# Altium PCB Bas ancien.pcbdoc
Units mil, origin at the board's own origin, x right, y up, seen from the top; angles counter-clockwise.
Board outline 2992.1 x 2852.4 mil, 2 copper layers (Top Layer, Bottom Layer), stack 62.2 mil thick; 28 components, 47 nets, 196 pads, 0 vias.
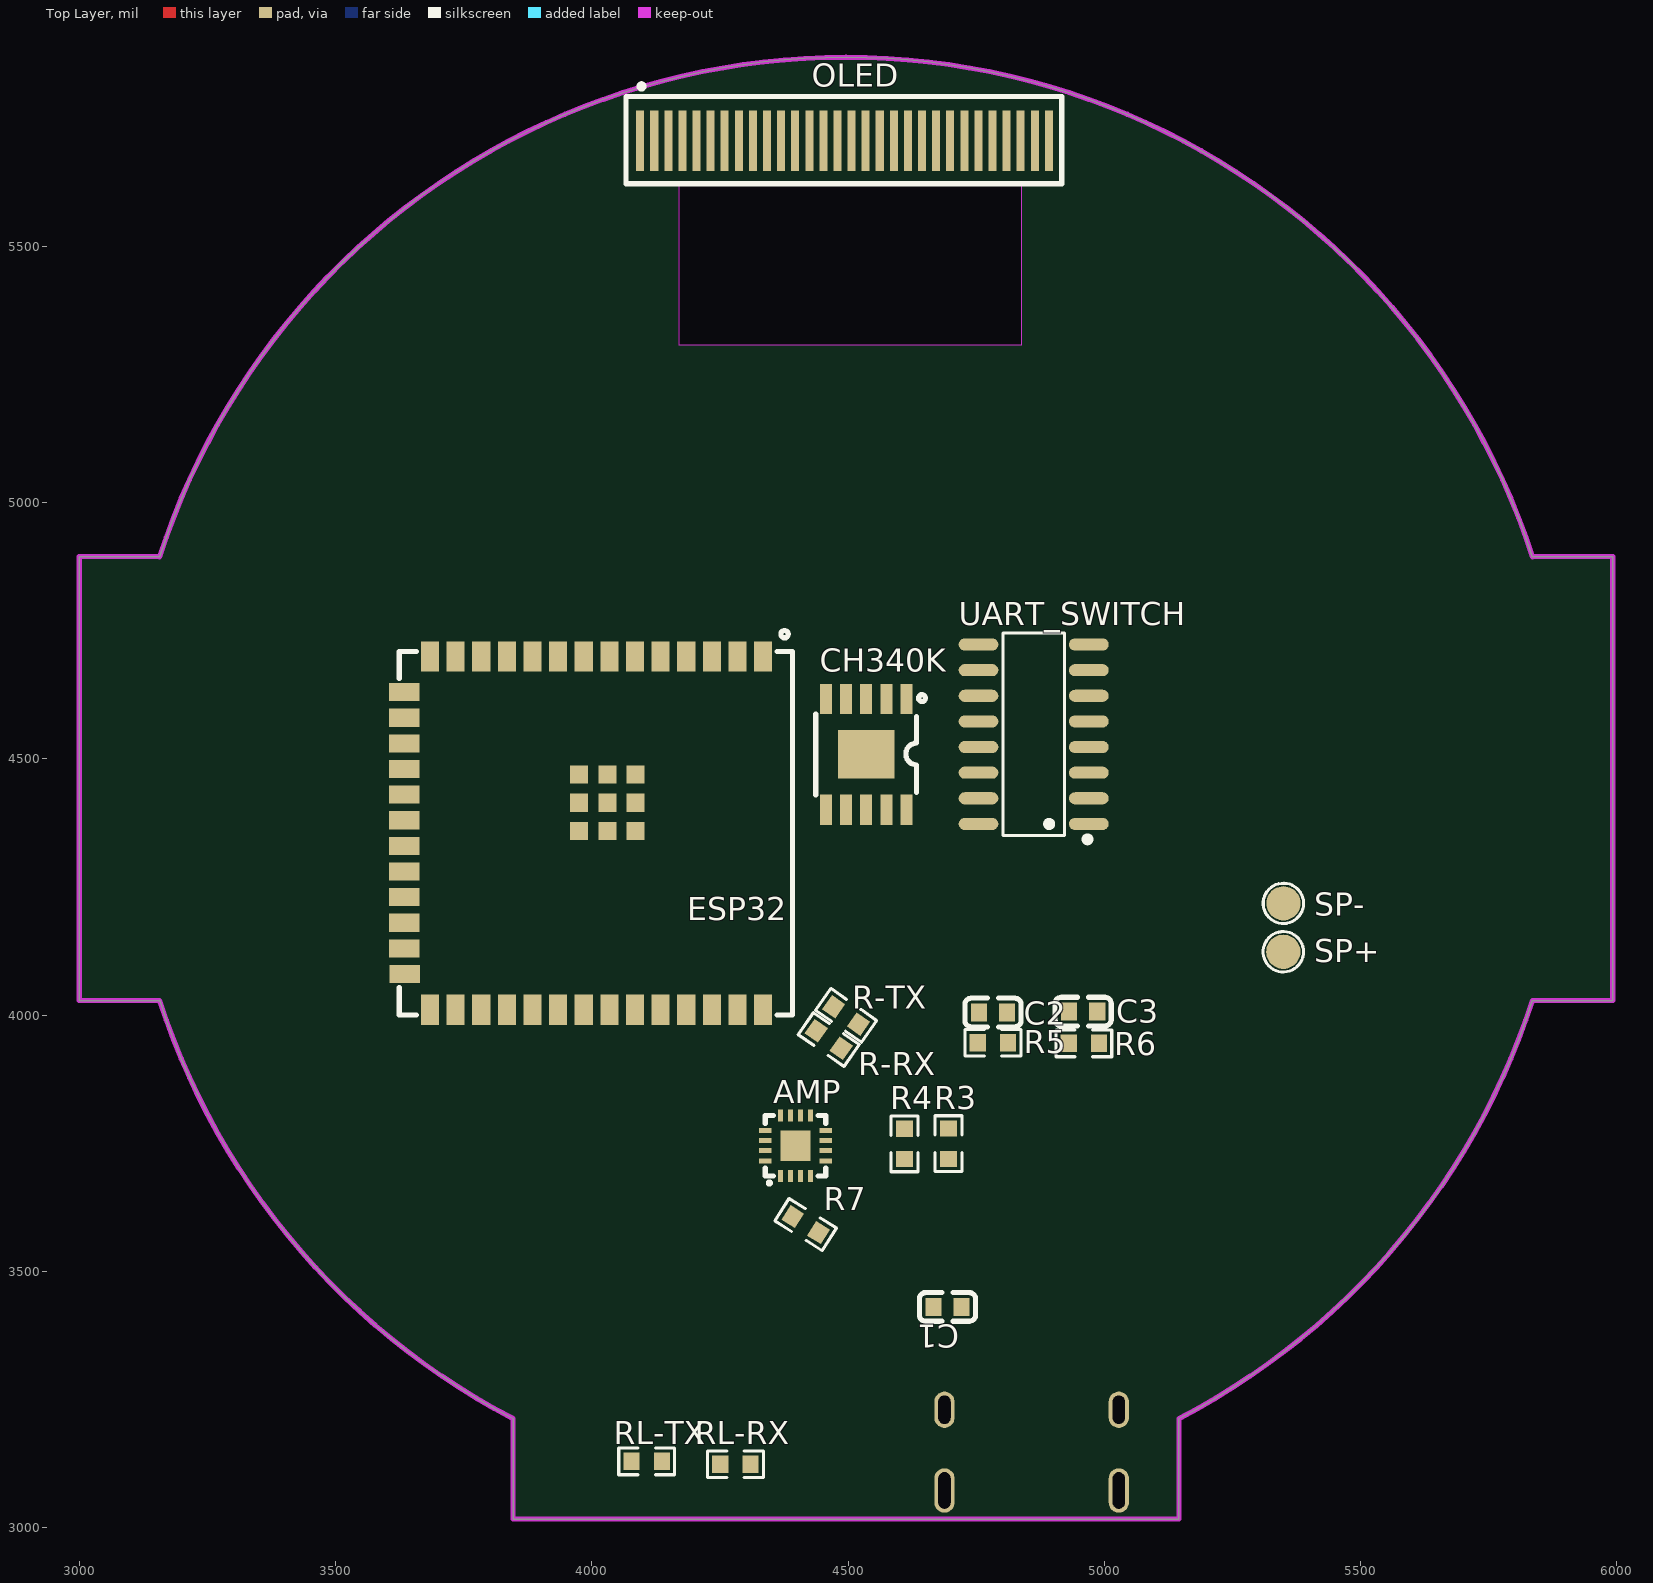
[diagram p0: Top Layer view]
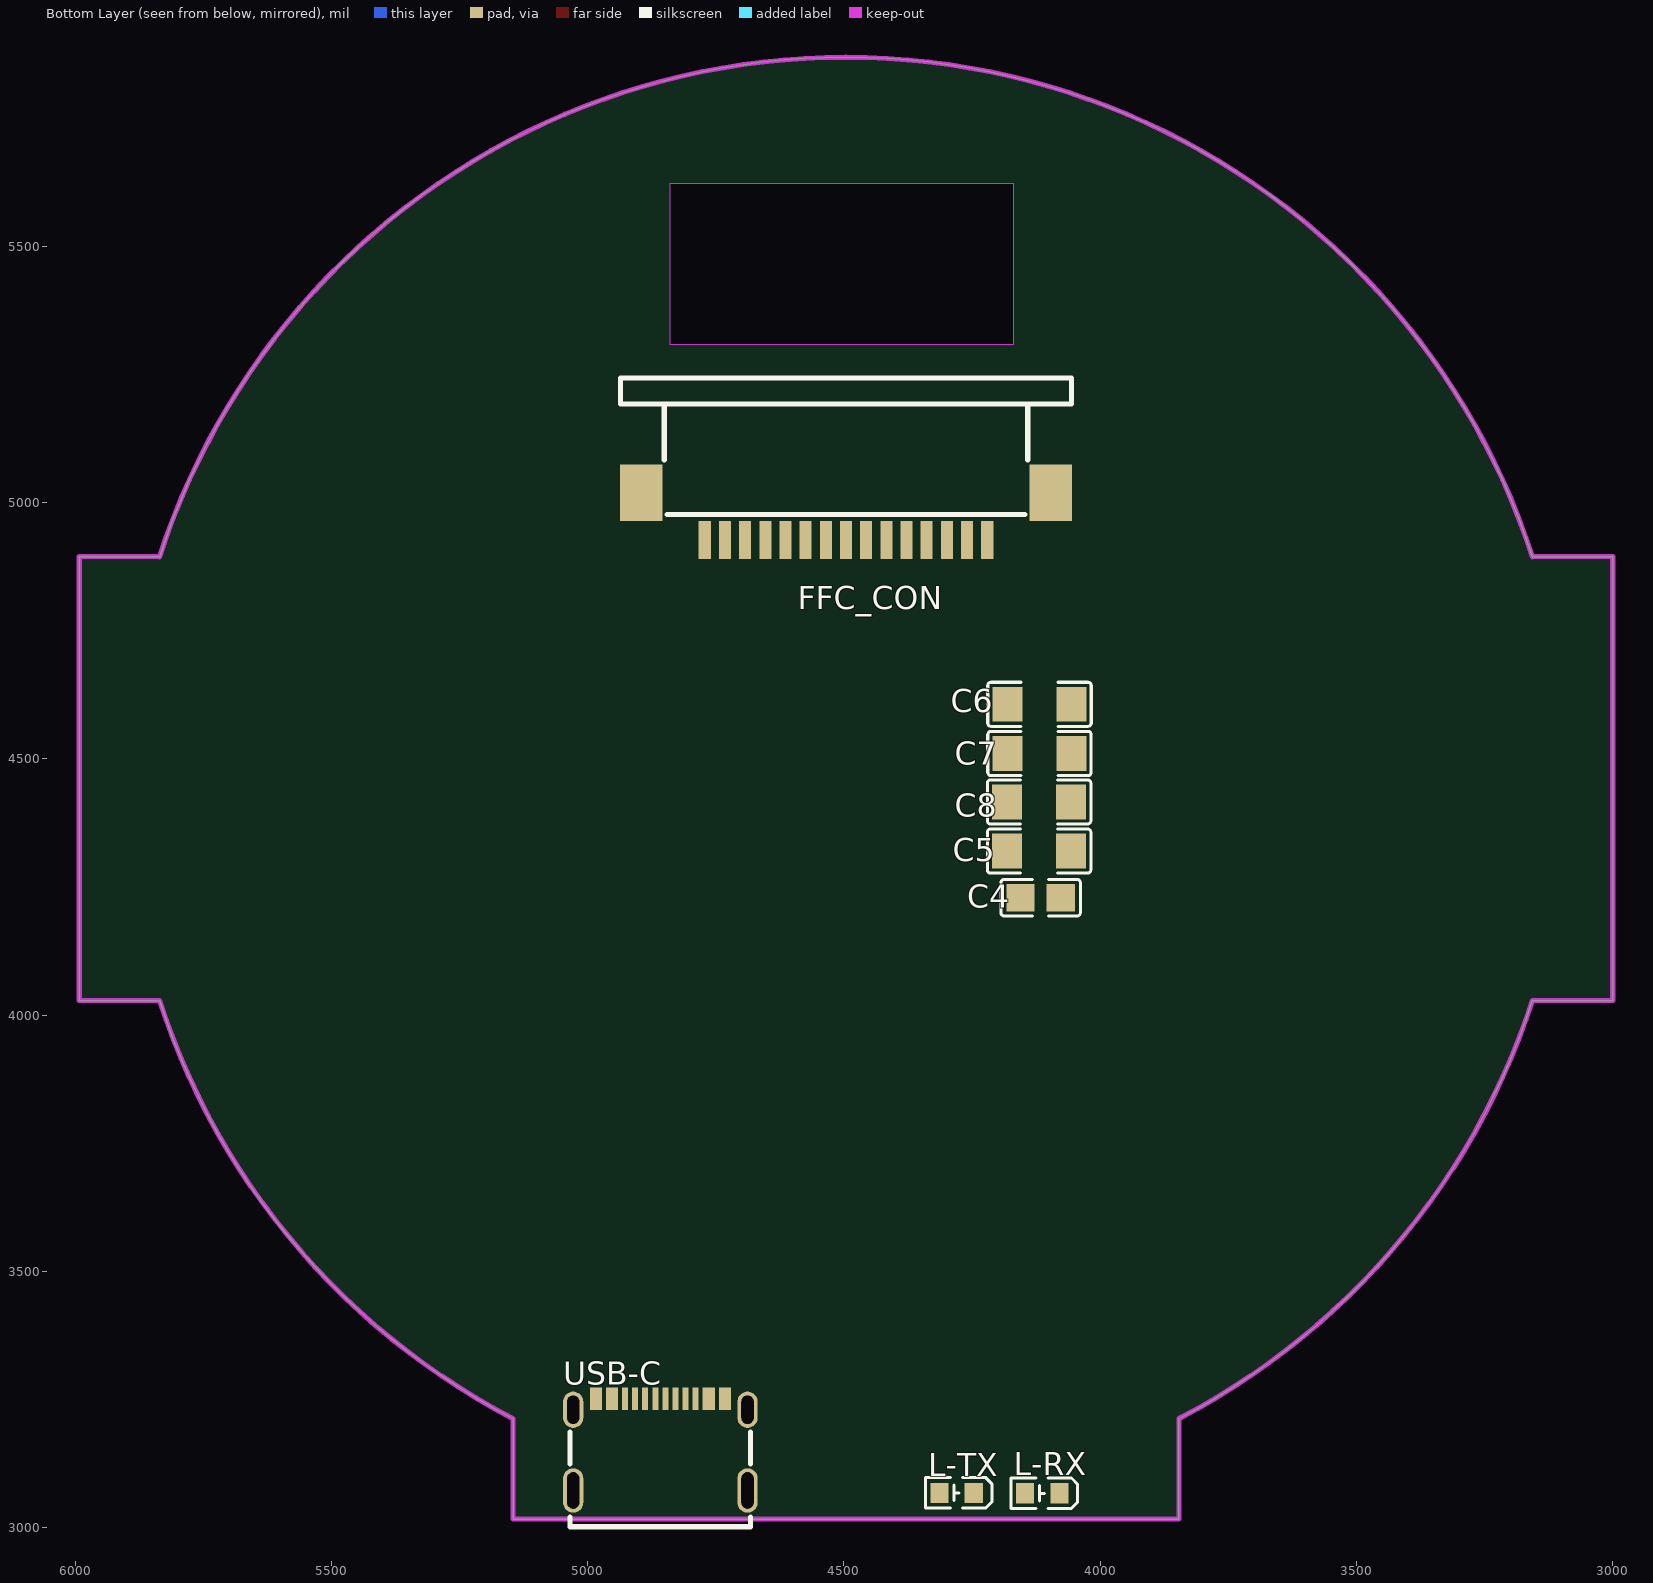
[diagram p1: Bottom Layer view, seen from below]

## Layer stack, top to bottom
Top Solder Mask Layer: solder mask 0.4, Dk 3.3
Top Layer: signal copper 1.4
Dielectric1: surface 59.4, FR4, Dk 4.5
Bottom Layer: signal copper 1.4
Bottom Solder Mask Layer: solder mask 0.4, Dk 3.3

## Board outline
3846.5,3016.8 3846.5,3213.1 cw(c4496.1,4461.7) 3156.9,4028.6 3000,4028.6 3000,4894.8 3156.9,4894.8 cw(c4496.1,4461.7) 4496.1,5869.2 cw(c4496.1,4461.7) 5835.3,4894.8 5992.1,4894.8 5992.1,4028.6 5835.3,4028.6 cw(c4496.1,4461.7) 5145.7,3213.1 5145.7,3016.8
cut-out: 4169.3,5623.1 4169.3,5308.1 4838.6,5308.1 4838.6,5623.1

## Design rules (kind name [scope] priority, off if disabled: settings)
BoardOutlineClearance copperThickness1oz [All] p0: genericclearance=10 ignorepadtopadclearanceinfootprint=FALSE except(0: Arc-SplitContinuation Track-SplitContinuation SMDPad-SplitContinuation THPad-SplitContinuation Via-SplitContinuation Fill-SplitContinuation Poly-SplitContinuation Region-SplitContinuation Text-SplitContinuation)
BoardOutlineClearance copperThickness2oz [All] p0: genericclearance=10 ignorepadtopadclearanceinfootprint=FALSE except(0: Arc-SplitContinuation Track-SplitContinuation SMDPad-SplitContinuation THPad-SplitContinuation Via-SplitContinuation Fill-SplitContinuation Poly-SplitContinuation Region-SplitContinuation Text-SplitContinuation)
BoardOutlineClearance Plane_innerPlane [All] p0: genericclearance=10 ignorepadtopadclearanceinfootprint=FALSE except(0: Arc-SplitContinuation Track-SplitContinuation SMDPad-SplitContinuation THPad-SplitContinuation Via-SplitContinuation Fill-SplitContinuation Poly-SplitContinuation Region-SplitContinuation Text-SplitContinuation)
BoardOutlineClearance Copper_copperRegion [All] p0: genericclearance=10 ignorepadtopadclearanceinfootprint=FALSE except(0: Arc-SplitContinuation Track-SplitContinuation SMDPad-SplitContinuation THPad-SplitContinuation Via-SplitContinuation Fill-SplitContinuation Poly-SplitContinuation Region-SplitContinuation Text-SplitContinuation)
BoardOutlineClearance otherClearance [All] p0: genericclearance=10 ignorepadtopadclearanceinfootprint=FALSE except(0: Arc-SplitContinuation Track-SplitContinuation SMDPad-SplitContinuation THPad-SplitContinuation Via-SplitContinuation Fill-SplitContinuation Poly-SplitContinuation Region-SplitContinuation Text-SplitContinuation)
Clearance copperThickness1oz [All] p1: gap=7 ignorepadtopadclearanceinfootprint=FALSE
Clearance copperThickness2oz [All] p1: gap=7 ignorepadtopadclearanceinfootprint=FALSE
Clearance Plane_innerPlane [All] p1: gap=7 ignorepadtopadclearanceinfootprint=FALSE
Clearance Copper_copperRegion [All] p1: gap=7 ignorepadtopadclearanceinfootprint=FALSE
Clearance otherClearance [All] p1: gap=7 ignorepadtopadclearanceinfootprint=FALSE
DiffPairsRouting differentialPair [All] p1: maxuncoupledlength=10 minlimit=6 maxlimit=Infinity mostfreqgap=6 toplayer_minwidth=5 toplayer_prefwidth=10 toplayer_maxwidth=100 bottomlayer_minwidth=5 bottomlayer_prefwidth=10 bottomlayer_maxwidth=100
PasteMaskExpansion pasteMaskExpansion [All] p1: expansion=0
PlaneConnect innerPlane [All] p1: planeconnectstyle=Relief reliefexpansion=20 reliefentries=4 reliefconductorwidth=10 reliefairgap=10
PolygonConnect copperRegion [All] p1: connectstyle=Relief reliefentries=4 reliefconductorwidth=10 polygonreliefangle="90 Angle" airgapwidth=10
RoutingVias viaSize [All] p1: viastyle="Through Hole" holewidth=12.0078 minholewidth=11.811 maxholewidth=248.0314 width=12.0078 minwidth=11.811 maxwidth=248.0314
SolderMaskExpansion solderMaskExpansion [IsVia] p1: useseparateexpansions=TRUE expansion=-1000 expansionbottom=-1000
SolderMaskExpansion solderMaskExpansion [All] p2: useseparateexpansions=TRUE expansion=2 expansionbottom=2
Width copperThickness1oz [All] p1: maxlimit=100 minlimit=5 preferedwidth=10
Width copperThickness2oz [All] p1: maxlimit=100 minlimit=8 preferedwidth=10

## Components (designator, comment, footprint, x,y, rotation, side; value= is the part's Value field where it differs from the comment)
AMP "MAX98357AETE+T" TQFN-16_L3.0-W3.0-P0.50-BL-EP1.5 4397.6,3745.4 r0 top
C1 "100nF" C0603#1 4694,3430.8 r0 top
C2 "100nF" C0603#2 4783,4005.4 r0 top
C3 "100nF" C0603#2 4958.8,4007.1 r0 top
C4 "100nF" C0805 4116.2,4229.3 r180 bottom
C5 "10uF" C1206 4119.4,4320.3 r180 bottom
C6 "4.7uF" C1206 4118.6,4606.7 r180 bottom
C7 "4.7uF" C1206 4118.6,4510.8 r180 bottom
C8 "4.7uF" C1206 4119.4,4416.2 r180 bottom
CH340K "CH340K" ESOP-10_L4.9-W3.9-P1.00-LS6.2-BL-EP 4535.4,4508.9 r180 top
ESP32 "ESP32-S3-WROOM-1U-N16R8" WIRELM-SMD_ESP32-S3-WROOM-1U 3984.3,4355.4 r270 top
FFC_CON "0522711579" CONN-SMD_0522711579 4496.1,4973.5 r0 bottom
L-RX "YLED0603O" LED0603-FD#1 4113.3,3067.4 r180 bottom
L-TX "YLED0603O" LED0603-FD#2 4280.3,3068.1 r180 bottom
OLED "SSD1306-128x64-OLED" SSD1306-128X64-OLED 4066.9,5792.4 r0 top
R3 "5.1kΩ" R0603_1#1 4696.1,3749.3 r270 top
R4 "5.1kΩ" R0603_1#2 4610.2,3749.1 r270 top
R5 "10kΩ" R0603#1 4782.6,3946.1 r180 top
R6 "10kΩ" R0603#2 4960,3945 r180 top
R7 "10kΩ" R0603#2 4417.3,3591.6 r148 top
R-RX "1kΩ" R0603_1#3 4462.4,3952.5 r145 top
R-TX "1kΩ" R0603_1#1 4496.2,3999.8 r145 top
RL-RX "150Ω" R0603#1 4280.2,3124.1 r180 top
RL-TX "150Ω" R0603#1 4107.3,3129.4 r180 top
SP+ "YZR0020-15025-01" SMD_YZR0020-15025-01 5349.3,4123.8 r0 top
SP- "YZR0020-15025-01" SMD_YZR0020-15025-01 5349.5,4218.3 r0 top
UART_SWITCH "CD74HC4052M" SOIC-16_L9.9-W3.9-P1.27-LS6.0-BL 4862.2,4548.3 r90 top
USB-C "UC.01.51-11-0017,typec" TYPE-C-SMD_UC.01.51-11-0017 4858.3,3162.5 r180 bottom

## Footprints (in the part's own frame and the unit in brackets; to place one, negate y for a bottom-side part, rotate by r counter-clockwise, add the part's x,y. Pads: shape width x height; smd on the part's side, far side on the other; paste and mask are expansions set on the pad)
C0603#1 [mil]
  rect 31.5x35.4 smd: 1(-27.5,0) 2(27.6,0)
  silkscreen extent -55,-28 55,28
C0603#2 [mil]
  rect 31.5x35.4 smd: 1(-27.6,0) 2(27.5,0)
  silkscreen extent -55,-28 55,28
C0805 [mil]
  rect 55.5x53.1 smd paste-3937 mask+2: 1(-39.4,0) 2(39.3,0)
  silkscreen extent -77,-36 77,36
C1206 [mil]
  rect 58.5x68 smd paste-3937 mask+2: 1(-62.7,0) 2(62.7,0)
  silkscreen extent -101,-43 101,43
CONN-SMD_0522711579 [mil]
  rect 23.6x74.8 smd paste+0 mask+2: 1(-275.6,46.3) 2(-236.3,46.3) 3(-196.9,46.3) 4(-157.5,46.3) 5(-118.2,46.3) 6(-78.8,46.3) 7(-39.4,46.3) 8(0,46.3) 9(39.3,46.3) 10(78.7,46.3) 11(118.1,46.3) 12(157.4,46.3) 13(196.8,46.3) 14(236.2,46.3) 15(275.5,46.3)
  rect 82.7x110.2 smd paste+0 mask+2: 16(399.6,-46.3) 17(-399.6,-46.3)
  silkscreen extent -440,-270 440,-4
ESOP-10_L4.9-W3.9-P1.00-LS6.2-BL-EP [mil]
  rect 23.6x59.1 smd: 1(-78.8,-108.3) 2(-39.4,-108.3) 3(0,-108.3) 4(39.3,-108.3) 5(78.7,-108.3) 6(78.7,108.2) 7(39.3,108.2) 8(0,108.2) 9(-39.4,108.2) 10(-78.8,108.2)
  rect 110.2x94.5 smd: 11(0,0)
  silkscreen extent -116,-117 98,79
LED0603-FD#1 [mil]
  rect 35.4x39.4 smd: 1(-33.5,0) 2(33.5,0)
  silkscreen extent -61,-30 69,30
LED0603-FD#2 [mil]
  rect 35.4x39.4 smd: 1(-33.4,0) 2(33.5,0)
  silkscreen extent -61,-30 69,30
R0603#1 [mil]
  rect 31.8x34 smd paste-3937 mask+2: 1(-29.6,0) 2(29.7,0)
  silkscreen extent -54,-26 55,26
R0603#2 [mil]
  rect 31.8x34 smd paste-3937 mask+2: 1(-29.7,0) 2(29.6,0)
  silkscreen extent -54,-26 54,26
R0603_1#1 [mil]
  rect 31.8x34 smd paste-3937 mask+2: 1(-29.7,0) 2(29.6,0)
  silkscreen extent -55,-26 55,26
R0603_1#2 [mil]
  rect 31.8x34 smd paste-3937 mask+2: 1(-29.7,0) 2(29.7,0)
  silkscreen extent -55,-26 55,26
R0603_1#3 [mil]
  rect 31.8x34 smd paste-3937 mask+2: 1(-29.66,-0.01) 2(29.71,-0.07)
  silkscreen extent -54,-26 55,26
SMD_YZR0020-15025-01 [mil]
  round 66.9 smd: 1(0,0)
  silkscreen extent -39,-39 39,39
SOIC-16_L9.9-W3.9-P1.27-LS6.0-BL [mil]
  oval 23.7x77.6 smd: 1(-175,-107.7) 2(-125,-107.7) 3(-75,-107.7) 4(-25,-107.7) 5(25,-107.7) 6(75,-107.7) 7(125,-107.7) 8(175,-107.7) 9(175,107.7) 10(125,107.7) 11(75,107.7) 12(25,107.7) 13(-25,107.7) 14(-75,107.7) 15(-125,107.7) 16(-175,107.7)
  silkscreen extent -211,-111 198,60
SSD1306-128X64-OLED [mil]
  rect 15.7x118.1 smd paste+0 mask+4: 1(27.5,-86) 2(55,-86) 3(82.5,-86) 4(110,-86) 5(137.5,-86) 6(165,-86) 7(192.5,-86) 8(220,-86) 9(247.5,-86) 10(275,-86) 11(302.5,-86) 12(330,-86) 13(357.5,-86) 14(385,-86) 15(412.5,-86) 16(440,-86) 17(467.5,-86) 18(495,-86) 19(522.5,-86) 20(550,-86) 21(577.5,-86) 22(605,-86) 23(632.5,-86) 24(660,-86) 25(687.5,-86) 26(715,-86) 27(742.5,-86) 28(770,-86) 29(797.5,-86) 30(825,-86)
  silkscreen extent 0,-170 850,25
TQFN-16_L3.0-W3.0-P0.50-BL-EP1.5 [mil]
  rect 9.8x23.6 smd paste-3937 mask+2: 1(-29.5,-59) 2(-9.8,-59) 3(9.9,-59) 4(29.5,-59) 9(29.5,59.1) 10(9.8,59.1) 11(-9.9,59.1) 12(-29.5,59.1)
  rect 23.6x9.8 smd paste-3937 mask+2: 5(59,-29.4) 6(59,-9.7) 7(59,10) 8(59,29.6) 13(-59.1,29.6) 14(-59.1,10) 15(-59.1,-9.7) 16(-59.1,-29.4)
  rect 59.1x59.1 smd paste-3937 mask+2: 17(0,0)
  silkscreen extent -59,-75 59,59
TYPE-C-SMD_UC.01.51-11-0017 [mil]
  rect 23.6x44.1 smd paste-3937 mask+2: A1B12(-125.9,89.6) A4B9(-94.4,89.6) B1A12(126,89.6) B4A9(94.5,89.6)
  rect 11.8x44.1 smd paste-3937 mask+2: A5(-49.2,89.6) A6(-9.8,89.6) A7(9.9,89.6) A8(49.3,89.6) B5(68.9,89.6) B6(29.6,89.6) B7(-29.5,89.6) B8(-68.9,89.6)
  oval 39.4x86.6 hole 23.6 slot 70.9 at 90 deg: EH1(-170,-89.7) EH1(170.1,-89.7)
  oval 39.4x70.9 hole 23.6 slot 55.1 at 90 deg: EH1(-170,67.8) EH1(170.1,67.8)
  silkscreen extent -176,-161 176,24
WIRELM-SMD_ESP32-S3-WROOM-1U [mil]
  rect 59.1x35.4 smd paste+0 mask+2: 1(-344.5,350.1) 2(-344.5,300.1) 3(-344.5,250.1) 4(-344.5,200.1) 5(-344.5,150.1) 6(-344.5,100.1) 7(-344.5,50.1) 8(-344.5,0.1) 9(-344.5,-49.9) 10(-344.5,-99.9) 11(-344.5,-149.9) 12(-344.5,-199.9) 13(-344.5,-249.9) 14(-344.5,-299.9) 27(344.5,-299.9) 28(344.5,-249.9) 29(344.5,-199.9) 30(344.5,-149.9) 31(344.5,-99.9) 32(344.5,-49.9) 33(344.5,0.1) 34(344.5,50.1) 35(344.5,100.1) 36(344.5,150.1) 37(344.5,200.1) 38(344.5,250.1) 39(344.5,300.1) 40(344.5,350.1)
  rect 35.4x59.1 smd paste+0 mask+2: 15(-275,-350.2) 16(-225,-350.2) 17(-175,-350.2) 18(-125,-350.2) 19(-75,-350.2) 20(-25,-350.2) 21(25,-350.2) 22(75,-350.2) 23(125,-350.2) 24(175,-350.2) 25(225,-350.2) 26(275,-349.1)
  rect 35.4x35.4 smd: 41(-114.2,46.2) 41(-114.2,101.3) 41(-114.2,-8.9) 41(-59.1,101.3) 41(-59.1,46.2) 41(-59.1,-8.9) 41(-3.9,101.3) 41(-3.9,46.2) 41(-3.9,-8.9)
  silkscreen extent -395,-360 355,408

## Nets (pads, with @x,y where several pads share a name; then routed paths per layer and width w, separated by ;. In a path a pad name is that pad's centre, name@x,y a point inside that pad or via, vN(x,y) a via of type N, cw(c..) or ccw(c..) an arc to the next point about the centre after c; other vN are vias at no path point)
3V3: C4.2 C5.2 ESP32.2 FFC_CON.3 OLED.6 OLED.9 OLED.13 OLED.17 OLED.28 R5.2 R6.2 UART_SWITCH.16
5V: AMP.7 AMP.8 C1.2 CH340K.7 FFC_CON.2 USB-C.A4B9 USB-C.B4A9
$1N2005: R4.2 USB-C.B5
$1N2006: R3.2 USB-C.A5
$1N2659: L-TX.2 RL-RX.2
$1N2661: L-RX.2 RL-TX.2
$1N3188: CH340K.9 R-TX.1 RL-TX.1
$1N3195: CH340K.8 R-RX.1 RL-RX.1
$1N10391: C6.1 OLED.3
$1N10430: C7.2 OLED.4
$1N10435: C7.1 OLED.5
$1N10475: C8.2 OLED.27
$1N16572: AMP.10 SP-.1
$1N16577: AMP.9 SP+.1
$1N18664: AMP.2 R7.2
AMP_EN: AMP.4 ESP32.8
BCLK: AMP.16 ESP32.20
D+: CH340K.1 USB-C.A6 USB-C.B6
D-: CH340K.2 USB-C.A7 USB-C.B7
DTR: C3.2 CH340K.4 R6.1
EN: C3.1 ESP32.3
GND: AMP.3 AMP.11 AMP.15 AMP.17 C1.1 C4.1 C5.1 C8.1 CH340K.3 ESP32.1 ESP32.40 ESP32.41 FFC_CON.1 FFC_CON.15 FFC_CON.16 FFC_CON.17 L-RX.1 L-TX.1 OLED.1 OLED.8 OLED.10 OLED.11 OLED.12 OLED.16 OLED.19 OLED.20 OLED.29 OLED.30 R3.1 R4.1 R7.1 UART_SWITCH.6 UART_SWITCH.8 UART_SWITCH.9 USB-C.A1B12 USB-C.B1A12
I2S: AMP.1 ESP32.22
IO0: C2.1 ESP32.27
LED: ESP32.35 FFC_CON.6
LRCLK: AMP.14 ESP32.21
MIC1: FFC_CON.7
MIC2: FFC_CON.8
MIC3: FFC_CON.9
MIC4: FFC_CON.10
NET2: UART_SWITCH.15
NET3: UART_SWITCH.14
NET4: UART_SWITCH.13
NET5: UART_SWITCH.12
NET6: UART_SWITCH.11
NET7: UART_SWITCH.1
NET8: UART_SWITCH.2
NET9: UART_SWITCH.3
NET10: UART_SWITCH.4
NET11: UART_SWITCH.5
NET12: UART_SWITCH.10
RESET_OLED1: ESP32.9 OLED.14
RTS: C2.2 CH340K.6 R5.1
RX: ESP32.36 R-RX.2
SCL: ESP32.17 FFC_CON.5 OLED.18
SDA: ESP32.12 FFC_CON.4 OLED.15
TX: ESP32.37 R-TX.2
pads on no net: AMP.5 AMP.6 AMP.12 AMP.13 C6.2 CH340K.5 CH340K.10 CH340K.11 ESP32.4 ESP32.5 ESP32.6 ESP32.7 ESP32.10 ESP32.11 ESP32.13 ESP32.14 ESP32.15 ESP32.16 ESP32.18 ESP32.19 ESP32.23 ESP32.24 ESP32.25 ESP32.26 ESP32.28 ESP32.29 ESP32.30 ESP32.31 ESP32.32 ESP32.33 ESP32.34 ESP32.38 ESP32.39 FFC_CON.11 FFC_CON.12 FFC_CON.13 FFC_CON.14 OLED.2 OLED.7 OLED.21 OLED.22 OLED.23 OLED.24 OLED.25 OLED.26 UART_SWITCH.7 USB-C.A8 USB-C.B8 USB-C.EH1

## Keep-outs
Board Outline Layer:
  region: 4169.3,5623.1 4169.3,5308.1 4838.6,5308.1 4838.6,5623.1
  region: 4169.3,5623.1 4169.3,5308.1 4838.6,5308.1 4838.6,5623.1
  lines w0.1: 4169.3,5308.1 4169.3,5623.1 4838.6,5623.1 4838.6,5308.1 4169.3,5308.1
  lines w10: 3156.73,4029.1 ccw(c4496.1,4461.7) 3846.19,3213.23 ; 3156.73,4894.3 cw(c4496.1,4461.7) 4496.1,5869.2 ; 5146.01,3213.23 ccw(c4496.1,4461.7) 5835.47,4029.1 ; 5835.3,4894.8 5992.1,4894.8 5992.1,4028.6 5835.3,4028.6 ; 5835.47,4894.3 ccw(c4496.1,4461.7) 4496.1,5869.2 ; 3156.9,4028.6 3156.9,4028.6 ; 3156.9,4028.6 3000,4028.6 3000,4894.8 3156.9,4894.8 ; 3156.9,4894.8 3156.9,4894.8 ; 3846.5,3213.1 3846.5,3016.8 5145.7,3016.8 5145.7,3213.1 ; 3846.5,3213.1 3846.5,3213.1 ; 4496.1,5869.2 4496.1,5869.2 ; 5145.7,3213.1 5145.7,3213.1 ; 5835.3,4028.6 5835.3,4028.6

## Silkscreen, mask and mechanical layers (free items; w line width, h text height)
Mechanical Layer:
  lines w0.1: 4169.3,5308.1 4169.3,5623.1 4838.6,5623.1 4838.6,5308.1 4169.3,5308.1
